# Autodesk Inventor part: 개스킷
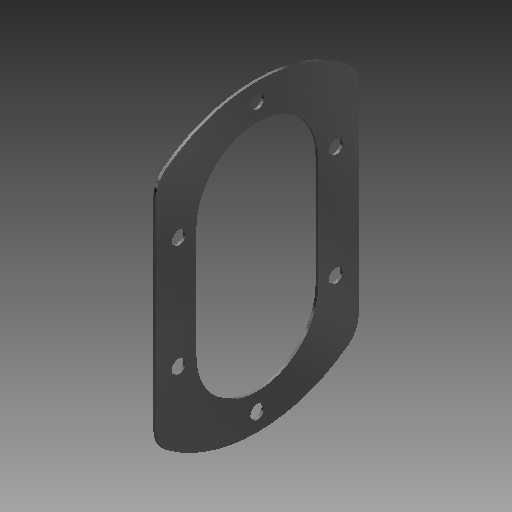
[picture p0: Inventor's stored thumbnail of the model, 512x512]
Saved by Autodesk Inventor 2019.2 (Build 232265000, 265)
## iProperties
Created: 2019-03
Part Number: 개스킷
Material: 고무
Document SubType Name: Modeling
Designer: mduedu
Density: 1 g/cm^3
Appearance: 고무 - 검은색 - 버전 1.1
Author: mduedu
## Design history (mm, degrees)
sketch "스케치1"
  geometry: L1 (-44.721, -40)-(44.721, -40); L2 (44.721, 40)-(-44.721, 40); A1 r 60 centre (0, 0) between (44.721, -40) and (44.721, 40); A2 r 60 centre (0, 0) between (-44.721, 40) and (-44.721, -40); 5 further points
  constraints: 6 point on circle, 4 end point, 2 centre point, 2 coincident, 2 horizontal alignment, 2 midpoint, 2 vertical alignment, 1 horizontal, 1 parallel
  dimensions: "d0" = 60 radius of A1; "d2" = 80 distance between parallel lines of L2 L1
extrude "돌출1" new body sketch "스케치1" distance "d3" = 1; taper "d4" = 0 deg
fillet "모깎기1" dims "d5" = 10
sketch "스케치2" dims "d6" = 48
  geometry: L1 (-24, -22)-(24, -22); L2 (24, -22)-(24, 22); L3 (24, 22)-(-24, 22); L4 (-24, 22)-(-24, -22); L5 (-24, -22)-(24, 22); L6 (24, -22)-(-24, 22); 3 further points
  constraints: 12 end point, 4 midpoint, 2 horizontal alignment, 2 parallel, 1 horizontal, 1 perpendicular, 4 other
  dimensions: "d8" = 22 distance from line of L3 point (0, 0)
extrude "돌출2" cut sketch "스케치2" extent not by distance; stored distance "d9" = 1; taper "d10" = 0 deg
sketch "스케치3" dims "d0" = 60, "d2" = 80
  geometry: L1 (31, -22)-(31, 22); L2 (-31, 22)-(-31, -22); L3 (-31, -22)-(31, 22); L4 (31, -22)-(-31, 22); A1 r 31 centre (0, 22) between (31, 22) and (-31, 22); A2 r 31 centre (0, -22) between (-31, -22) and (31, -22); 8 further points
  constraints: 8 end point, 6 point on circle, 4 coincident, 4 midpoint, 3 tangent, 2 centre point, 2 vertical alignment, 1 parallel
  dimensions: "d11" = 31 radius of A1; "d13" = 44 distance of A2.centre A1.centre
hole "구멍1" sketch "스케치3" at (-31, 22), (-31, -22), (31, -22), (31, 22), (0, -53), (0, 53) diameter "d14" = 5.5; stored, may be unused: countersink angle "d18" = 90 deg, drill point angle "d20" = 118 deg; dims "d15" = 6, "d16" = 4, "d17" = 2, "d19" = 8
node "솔리드1"
